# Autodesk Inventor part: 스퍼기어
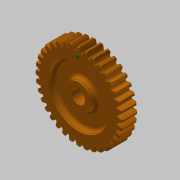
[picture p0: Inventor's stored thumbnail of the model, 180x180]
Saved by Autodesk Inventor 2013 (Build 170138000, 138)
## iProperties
Created: 2019-01
Part Number: 스퍼기어
Material: 알루미늄 6061
Document SubType Name: Modeling
Designer: mduedu
Density: 1 g/cm^3
Author: mduedu
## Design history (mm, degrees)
sketch "스케치1"
  geometry: C1 r 33.5 at (0, 0); C2 r 36 at (0, 0); C3 r 38 at (0, 0); 1 further point
  constraints: 3 centre point, 3 coincident
  dimensions: "d0" = 67 diameter of C1; "d2" = 72 diameter of C2; "d3" = 76 diameter of C3
extrude "돌출1" new body sketch "스케치1" distance "d4" = 14; taper "d5" = 0 deg
sketch "스케치2"
  geometry: L1 (0, 0)-(-38, 0); L2 (0, 0)-(0, 38); L3 (-0.57, 0)-(-0.57, 37.996); L4 (-1.57, 0)-(-1.57, 35.966); L5 (-2.07, 0)-(-2.07, 33.436); A1 r 38 centre (0, 0) between (-38, 0) and (0, 38) reference; A2 r 9.246 centre (7.162, 32.926) between (-0.57, 37.996) and (-2.07, 33.436); A3 r 9.246 centre (-7.162, 32.926) between (2.07, 33.436) and (0.57, 37.996); A4 r 33.5 centre (0, 0) between (2.07, 33.436) and (-2.07, 33.436); A5 r 38 centre (0, 0) between (0.57, 37.996) and (-0.57, 37.996); 2 further points
  constraints: 12 point on circle, 10 end point, 4 centre point, 3 parallel, 3 symmetric about line, 2 coincident, 1 horizontal, 1 perpendicular, 5 other
  dimensions: "d6" = 0.5 distance between parallel lines of L4 L5; "d8" = 1 distance between parallel lines of L3 L4; "d9" = 1.57 distance between parallel lines of L2 L4
extrude "돌출2" join sketch "스케치2" stored distance "d10" = 14; taper "d11" = 0 deg
chamfer "모따기1" distance "d12" = 1; stored, may be unused: second distance "d13" = 2, angle "d14" = 45 deg
fillet "모깎기1" dims "d15" = 0.5
sketch "스케치3"
  geometry: C1 r 11 at (0, 0); 1 further point
  constraints: 1 centre point, 1 coincident
  dimensions: "d19" = 22 diameter of C1
extrude "돌출3" join sketch "스케치3" distance "d20" = 7; taper "d21" = 0 deg
sketch "스케치4"
  geometry: C1 r 11 at (0, 0); C2 r 26 at (0, 0); 1 further point
  constraints: 2 centre point, 2 coincident
  dimensions: "d23" = 22 diameter of C1; "d24" = 52 diameter of C2
extrude "돌출4" cut sketch "스케치4" distance "d25" = 5; taper "d26" = 0 deg
fillet "모깎기3" dims "d27" = 3
node "작업 평면1"
sketch "스케치5" dims "d28" = 60
  geometry: C1 r 1.5 at (0, 30); 2 further points
  constraints: 2 vertical alignment, 1 centre point, 1 coincident, 2 other
  dimensions: "d29" = 3 diameter of C1
extrude "돌출5" join sketch "스케치5" distance "d30" = 0.5; taper "d31" = 0 deg
sketch "스케치6"
  geometry: L1 (-2, 5.657)-(2, 5.657); L2 (2, 5.657)-(2, 7.8); L3 (2, 7.8)-(-2, 7.8); L4 (-2, 7.8)-(-2, 5.657); A1 r 6 centre (0, 0) between (-2, 5.657) and (2, 5.657); 1 further point
  constraints: 8 end point, 2 parallel, 2 point on circle, 1 centre point, 1 coincident, 1 horizontal, 1 perpendicular
  dimensions: "d32" = 13.8 dimension on A1 L3; "d34" = 4 distance of L2.end L3.end; "d35" = 12 diameter of A1
extrude "돌출6" cut sketch "스케치6" stored distance "d36" = 0.5; taper "d37" = 0 deg
chamfer "모따기2" distance "d38" = 1; stored, may be unused: second distance "d39" = 2, angle "d40" = 45 deg
node "솔리드1"
pattern_circular "원형 패턴1" dims "d17" = 360 deg
mirror "대칭1"
